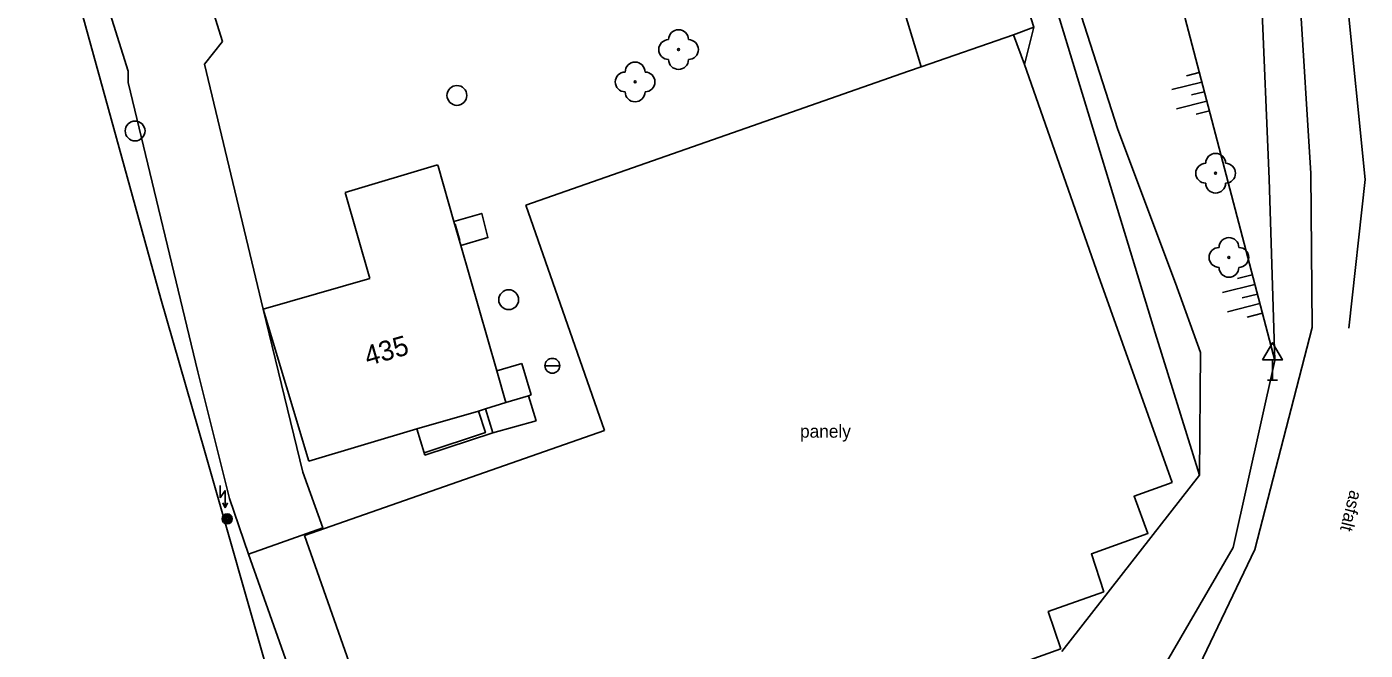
# Model space of a CAD drawing. Extents: x -539244 to -537359, y -1183785 to -1181851.
# Drawn here: x -537787.2 to -537719.8, y -1182100.3 to -1182068.9 of the extents above; entities that cross this region are included whole.
import ezdxf

# ---------------------------------------------------------------- set-up
doc = ezdxf.new("R2010")
doc.units = 0
for name, color, linetype in [('Vrstva 10', 7, 'Continuous'), ('Vrstva 11', 7, 'Continuous'), ('Vrstva 14', 7, 'Continuous'), ('Vrstva 15', 7, 'Continuous'), ('Vrstva 22', 7, 'Continuous'), ('Vrstva 24', 7, 'Continuous'), ('Vrstva 25', 7, 'Continuous'), ('Vrstva 27', 7, 'Continuous'), ('Vrstva 34', 7, 'Continuous'), ('Vrstva 35', 7, 'Continuous'), ('Vrstva 40', 7, 'Continuous'), ('Vrstva 47', 7, 'Continuous'), ('Vrstva 5', 7, 'Continuous'), ('Vrstva 6', 7, 'Continuous'), ('Vrstva 7', 7, 'Continuous')]:
    doc.layers.add(name, color=color, linetype=linetype)

msp = doc.modelspace()

# ---------------------------------------------------------------- linework, layer by layer
at = {"layer": 'Vrstva 10'}
for p, q in [((-537723.66, -1182057.46), (-537722.49, -1182076.32)), ((-537719.75, -1182076.62), (-537721.69, -1182057.3)), ((-537722.49, -1182076.32), (-537722.43, -1182084.08)), ((-537720.58, -1182084.11), (-537719.75, -1182076.62)), ((-537722.43, -1182084.08), (-537725.317, -1182095.266)), ((-537725.317, -1182095.266), (-537729.91, -1182104.84))]:
    msp.add_line(p, q, dxfattribs=at)
at = {"layer": 'Vrstva 11'}
for p, q in [((-537777.34, -1182069.67), (-537782.74, -1182052.43)), ((-537782.1, -1182071.16), (-537787.21, -1182054.82)), ((-537740.62, -1182055.51), (-537736.46, -1182068.95)), ((-537737.47, -1182069.33), (-537736.46, -1182068.95)), ((-537736.92, -1182070.83), (-537736.46, -1182068.95)), ((-537778.26, -1182070.82), (-537777.34, -1182069.67)), ((-537737.47, -1182069.33), (-537736.92, -1182070.83)), ((-537782.1, -1182071.74), (-537782.1, -1182071.16)), ((-537775.29, -1182083.16), (-537778.26, -1182070.82)), ((-537751.299, -1182074.154), (-537742.77, -1182071.17)), ((-537736.92, -1182070.83), (-537733.189, -1182081.484)), ((-537778.59, -1182086.32), (-537782.1, -1182071.74)), ((-537762.049, -1182077.914), (-537751.299, -1182074.154)), ((-537758.099, -1182089.264), (-537762.049, -1182077.914)), ((-537733.189, -1182081.484), (-537729.479, -1182091.884)), ((-537773.3, -1182091.37), (-537775.29, -1182083.16)), ((-537776.99, -1182092.69), (-537778.59, -1182086.32)), ((-537773.219, -1182094.564), (-537758.099, -1182089.264)), ((-537776.04, -1182095.5), (-537776.99, -1182092.69)), ((-537770.129, -1182103.294), (-537773.219, -1182094.564)), ((-537776.04, -1182095.5), (-537772.67, -1182105)), ((-537735.089, -1182100.274), (-537745.429, -1182103.944))]:
    msp.add_line(p, q, dxfattribs=at)
for points in [[(-537742.128, -1182070.947), (-537742.35, -1182070.22), (-537744.29, -1182063.87)], [(-537742.77, -1182071.17), (-537742.128, -1182070.947), (-537737.47, -1182069.33)], [(-537765.34, -1182079.945), (-537763.97, -1182079.55), (-537764.28, -1182078.33), (-537765.689, -1182078.736)], [(-537764.45, -1182088.29), (-537764.09, -1182089.37), (-537767.186, -1182090.39)], [(-537776.04, -1182095.5), (-537772.29, -1182094.18), (-537773.3, -1182091.37)], [(-537729.479, -1182091.884), (-537731.399, -1182092.584), (-537730.699, -1182094.454), (-537733.549, -1182095.484), (-537732.919, -1182097.394)], [(-537732.919, -1182097.394), (-537735.729, -1182098.394), (-537735.089, -1182100.274)]]:
    msp.add_lwpolyline(points, dxfattribs=at)
at = {"layer": 'Vrstva 14'}
for p, q in [((-537738.15, -1182055.69), (-537732.22, -1182074.11)), ((-537724.31, -1182085.74), (-537729.4, -1182066.33)), ((-537732.22, -1182074.11), (-537729.32, -1182081.84)), ((-537729.32, -1182081.84), (-537728.06, -1182085.34)), ((-537728.06, -1182085.34), (-537728.1, -1182091.52))]:
    msp.add_line(p, q, dxfattribs=at)
at = {"layer": 'Vrstva 15'}
for p, q in [((-537727.987, -1182071.72), (-537729.502, -1182072.099)), ((-537728.113, -1182071.236), (-537728.75, -1182071.396)), ((-537727.86, -1182072.204), (-537728.507, -1182072.366)), ((-537727.733, -1182072.687), (-537729.259, -1182073.069)), ((-537727.606, -1182073.171), (-537728.264, -1182073.336)), ((-537725.315, -1182081.909), (-537726.943, -1182082.318)), ((-537725.441, -1182081.426), (-537726.191, -1182081.614)), ((-537725.188, -1182082.393), (-537725.948, -1182082.584)), ((-537725.061, -1182082.877), (-537726.7, -1182083.288)), ((-537724.934, -1182083.361), (-537725.705, -1182083.554))]:
    msp.add_line(p, q, dxfattribs=at)
at = {"layer": 'Vrstva 22'}
for centre in [(-537754.36, -1182070.08), (-537756.55, -1182071.71), (-537727.29, -1182076.31), (-537726.62, -1182080.55)]:
    msp.add_circle(centre, 0.05, dxfattribs=at)
for centre, start, end in [((-537754.36, -1182069.58), 0, 180), ((-537754.86, -1182070.08), 90, 270), ((-537753.86, -1182070.08), 270, 90), ((-537757.05, -1182071.71), 90, 270), ((-537756.55, -1182071.21), 0, 180), ((-537756.05, -1182071.71), 270, 90), ((-537754.36, -1182070.58), 180, 0), ((-537756.55, -1182072.21), 180, 0), ((-537727.79, -1182076.31), 90, 270), ((-537727.29, -1182075.81), 0, 180), ((-537726.79, -1182076.31), 270, 90), ((-537727.29, -1182076.81), 180, 0), ((-537726.62, -1182080.05), 0, 180), ((-537727.12, -1182080.55), 90, 270), ((-537726.12, -1182080.55), 270, 90), ((-537726.62, -1182081.05), 180, 0)]:
    msp.add_arc(centre, 0.5, start, end, dxfattribs=at)
at = {"layer": 'Vrstva 24'}
for p, q in [((-537777.46, -1182092.034), (-537777.46, -1182092.66)), ((-537777.46, -1182092.66), (-537777.21, -1182092.285)), ((-537777.21, -1182092.285), (-537777.21, -1182093.16)), ((-537777.32, -1182092.915), (-537777.21, -1182093.16)), ((-537777.21, -1182093.16), (-537777.1, -1182092.915))]:
    msp.add_line(p, q, dxfattribs=at)
at = {"layer": 'Vrstva 25'}
for radius in [0.25, 0.2, 0.15, 0.1, 0.05]:
    msp.add_circle((-537777.11, -1182093.72), radius, dxfattribs=at)
at = {"layer": 'Vrstva 27'}
for centre in [(-537765.53, -1182072.39), (-537781.75, -1182074.18), (-537762.92, -1182082.68)]:
    msp.add_circle(centre, 0.5, dxfattribs=at)
at = {"layer": 'Vrstva 34'}
for p, q in [((-537724.42, -1182085.712), (-537724.42, -1182086.73)), ((-537724.67, -1182086.73), (-537724.17, -1182086.73))]:
    msp.add_line(p, q, dxfattribs=at)
msp.add_lwpolyline([(-537724.92, -1182085.712), (-537723.92, -1182085.712), (-537724.42, -1182084.846)], close=True, dxfattribs=at)
at = {"layer": 'Vrstva 35'}
msp.add_line((-537761.095, -1182086.01), (-537760.345, -1182086.01), dxfattribs=at)
msp.add_circle((-537760.72, -1182086.01), 0.375, dxfattribs=at)
at = {"layer": 'Vrstva 5'}
for p, q in [((-537766.51, -1182075.89), (-537771.17, -1182077.28)), ((-537766.51, -1182075.89), (-537766.47, -1182075.95)), ((-537766.47, -1182075.95), (-537765.689, -1182078.736)), ((-537771.17, -1182077.28), (-537769.921, -1182081.611)), ((-537765.689, -1182078.736), (-537765.34, -1182079.945)), ((-537765.34, -1182079.945), (-537763.516, -1182086.27)), ((-537769.921, -1182081.611), (-537775.29, -1182083.16)), ((-537775.29, -1182083.16), (-537773, -1182090.81)), ((-537763.516, -1182086.27), (-537762.25, -1182085.89)), ((-537762.25, -1182085.89), (-537761.78, -1182087.47)), ((-537763.516, -1182086.27), (-537763.057, -1182087.862)), ((-537763.057, -1182087.862), (-537764.089, -1182088.179)), ((-537761.928, -1182087.516), (-537763.057, -1182087.862)), ((-537761.78, -1182087.47), (-537761.928, -1182087.516)), ((-537761.928, -1182087.516), (-537761.54, -1182088.78)), ((-537767.544, -1182089.186), (-537764.45, -1182088.29)), ((-537764.089, -1182088.179), (-537764.45, -1182088.29)), ((-537763.72, -1182089.38), (-537764.089, -1182088.179)), ((-537773, -1182090.81), (-537767.544, -1182089.186)), ((-537767.544, -1182089.186), (-537767.186, -1182090.39)), ((-537767.15, -1182090.51), (-537763.72, -1182089.38)), ((-537761.54, -1182088.78), (-537763.72, -1182089.38)), ((-537767.186, -1182090.39), (-537767.15, -1182090.51))]:
    msp.add_line(p, q, dxfattribs=at)
at = {"layer": 'Vrstva 6'}
msp.add_line((-537765.39, -1182079.7), (-537765.61, -1182078.88), dxfattribs=at)
at = {"layer": 'Vrstva 7'}
for p, q in [((-537724.6, -1182076.59), (-537725.33, -1182058.62)), ((-537735.62, -1182066.98), (-537730.34, -1182084.35)), ((-537780.45, -1182082.64), (-537784.66, -1182067.41)), ((-537724.31, -1182085.74), (-537724.6, -1182076.59)), ((-537778.26, -1182090.28), (-537780.45, -1182082.64)), ((-537730.34, -1182084.35), (-537728.1, -1182091.52)), ((-537724.31, -1182085.74), (-537726.4, -1182095.16)), ((-537773.79, -1182105.85), (-537778.26, -1182090.28)), ((-537728.1, -1182091.52), (-537735.04, -1182100.4)), ((-537726.4, -1182095.16), (-537733.01, -1182106.49))]:
    msp.add_line(p, q, dxfattribs=at)

# ---------------------------------------------------------------- texts
at = {"layer": 'Vrstva 40'}
msp.add_text('panely', height=0.65, dxfattribs=at).set_placement((-537748.236, -1182089.631))
msp.add_text('asfalt', height=0.65, rotation=255.7927, dxfattribs=at).set_placement((-537720.513, -1182092.239))
at = {"layer": 'Vrstva 47'}
msp.add_text('435', height=1, rotation=16.00204, dxfattribs=at).set_placement((-537770.025, -1182086.027))

doc.saveas('drawing.dxf')
